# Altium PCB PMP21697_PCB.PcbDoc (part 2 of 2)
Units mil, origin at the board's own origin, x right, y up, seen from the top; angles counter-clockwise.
Board outline 4950 x 3450 mil, 6 copper layers (Top Layer, Signal Layer 1, Signal Layer 2, Signal Layer 3, Signal Layer 4, Bottom Layer), stack 60.502 mil thick; 163 components, 60 nets, 332 pads, 953 vias.
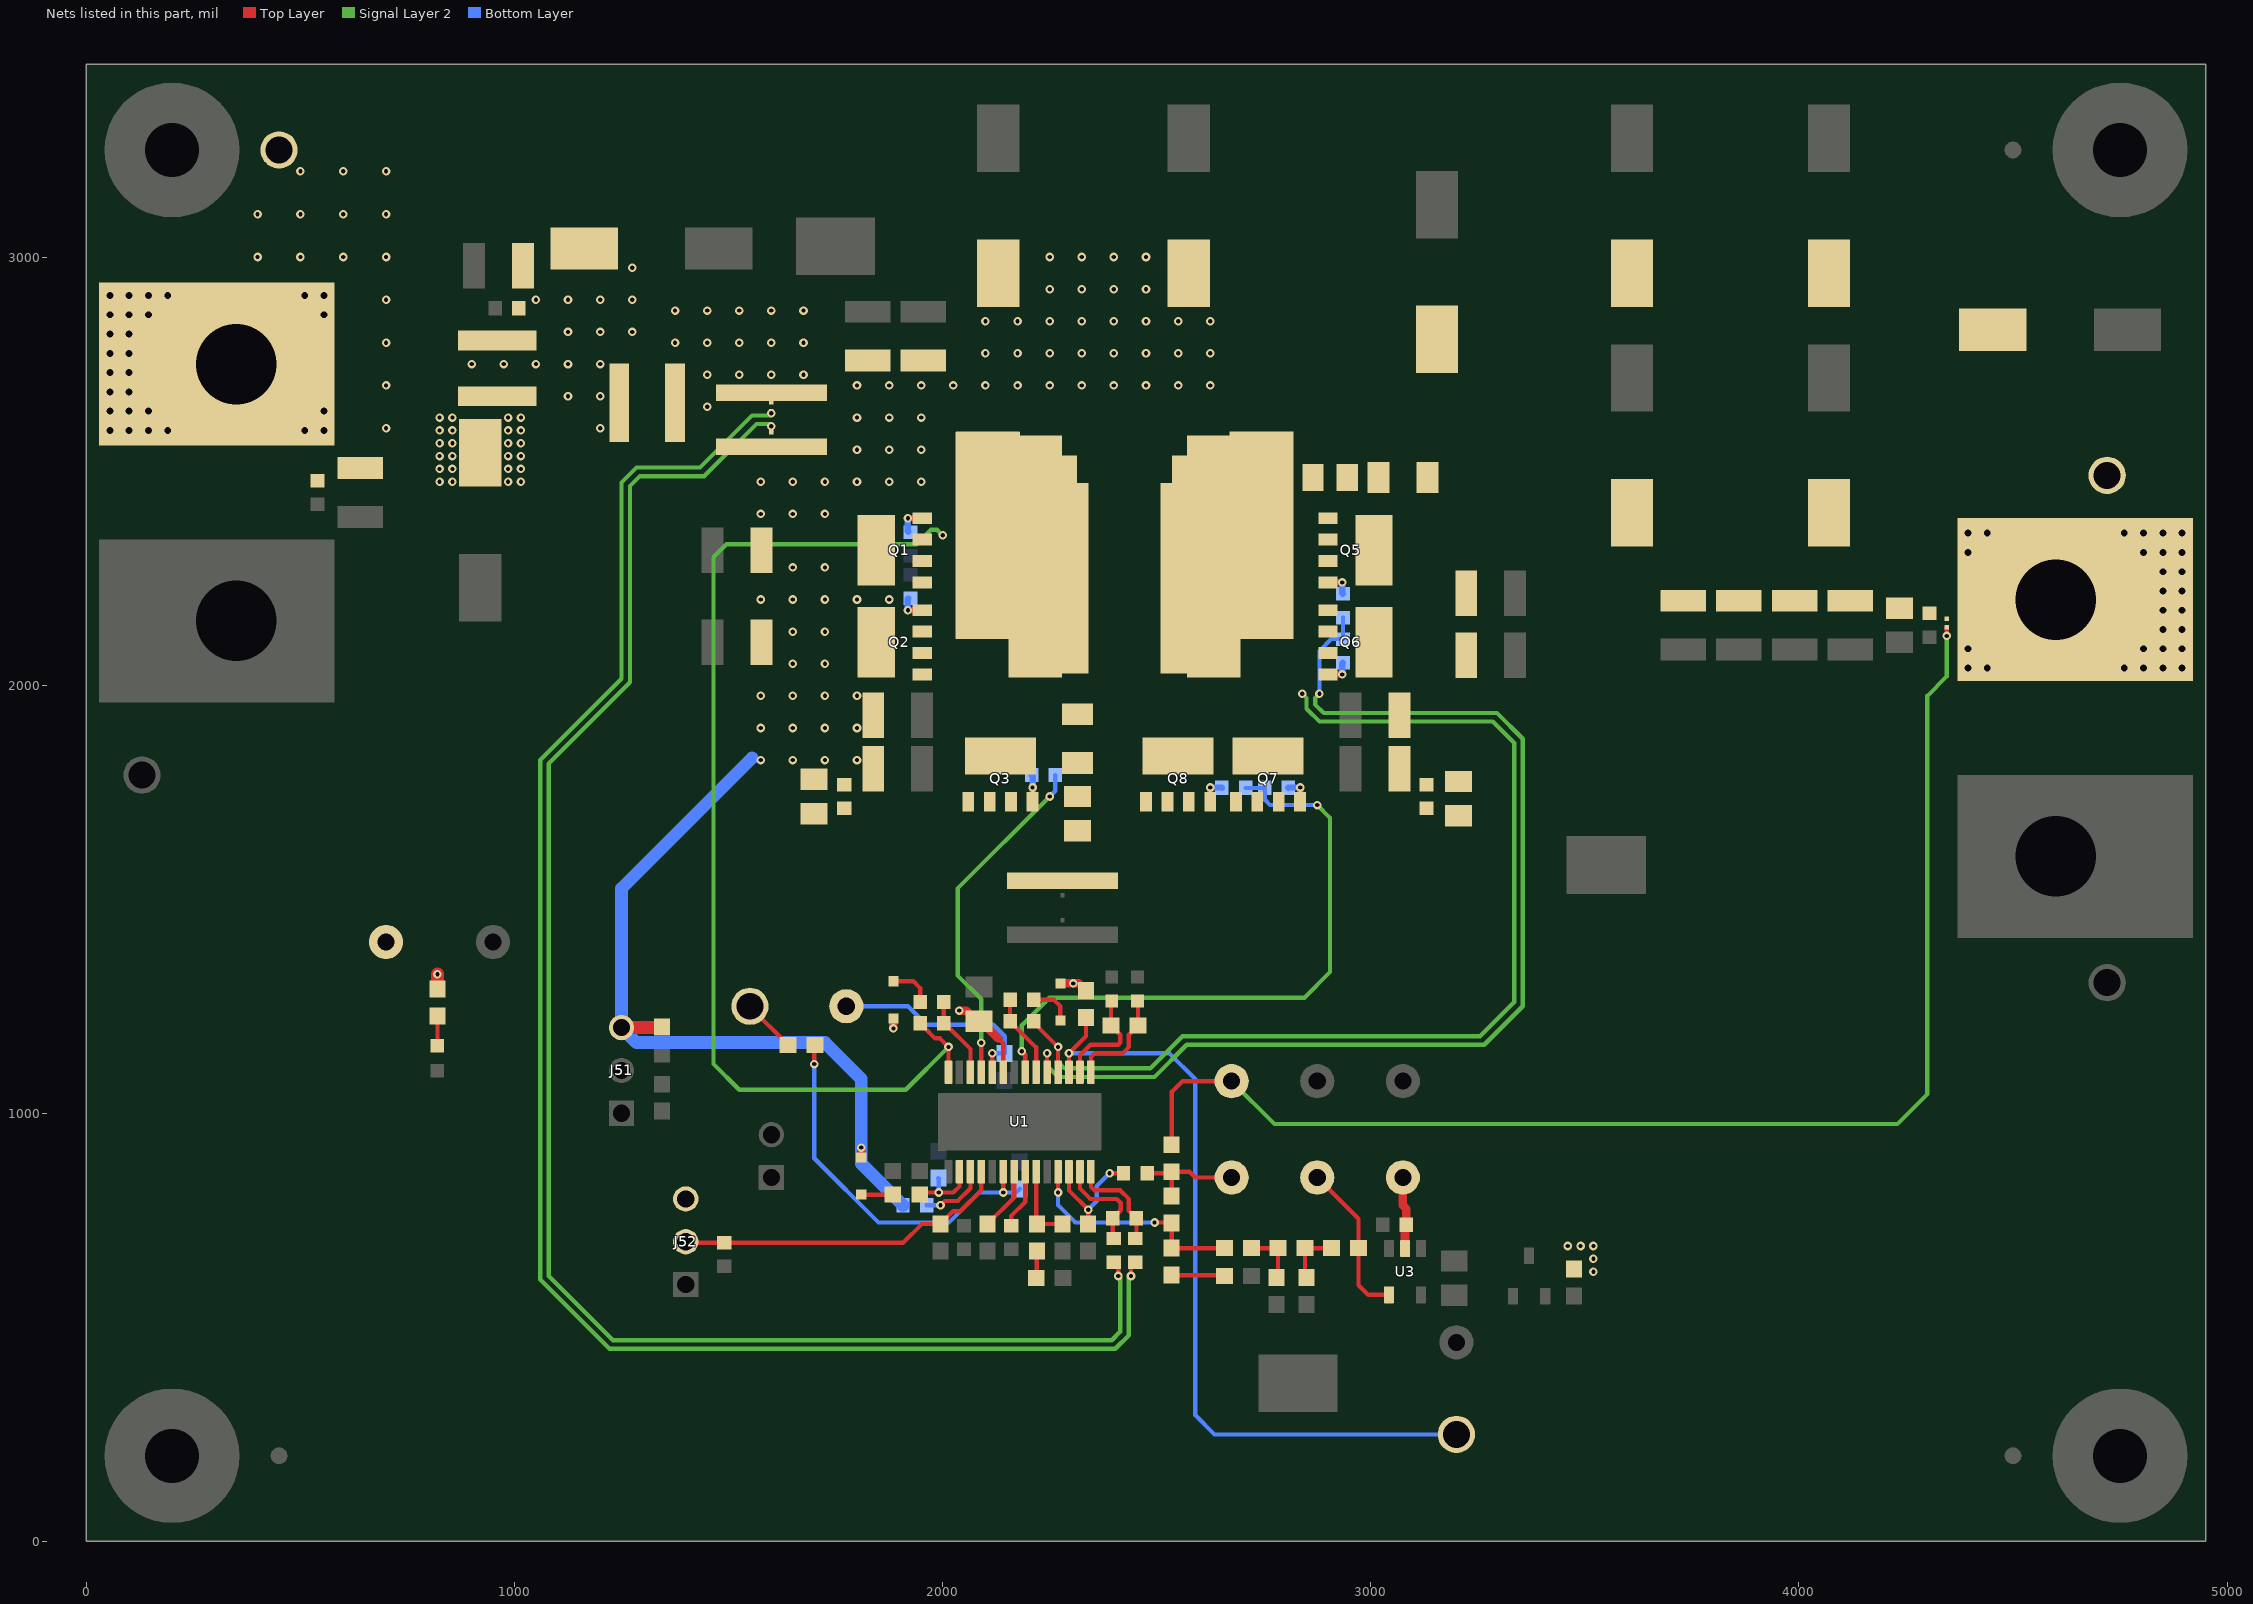
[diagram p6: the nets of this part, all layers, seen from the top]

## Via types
v1: diameter 20, hole 10, Top Layer to Bottom Layer, tented both sides, 820 vias
v2: diameter 32, hole 16, Top Layer to Bottom Layer, 112 vias
v3: diameter 19.68, hole 7.87, Top Layer to Bottom Layer, tented both sides, 12 vias
v4: diameter 19.68, hole 7.87, Top Layer to Bottom Layer, 9 vias

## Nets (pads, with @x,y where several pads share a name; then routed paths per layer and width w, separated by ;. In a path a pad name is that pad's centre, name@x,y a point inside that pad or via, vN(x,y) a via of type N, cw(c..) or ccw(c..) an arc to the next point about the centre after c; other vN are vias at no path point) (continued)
HO2: R15.2 R16.2 U1.19 | length 2652
  Top Layer w10: U1.19@2243.98,1096.14 v1(2243.98,1140)
  Signal Layer 2 w10: v1(2243.98,1140) 2243.98,1111.02 2270,1085 2495,1085 2570,1160 3265,1160 3355,1250 3355,1875 3295,1935 2890,1935 2870,1955 2870,1970 v1(2880,1980)
  Bottom Layer w10: v1(2880,1980) 2880,2080 2907.56,2107.56 R16.2@2935,2107.56 R15.2@2935,2157.93
LO1: R13.2 U1.25 | length 811.4
  Top Layer w10: U1.25@2090.43,1096.14 v1(2090.43,1165)
  Signal Layer 2 w10: v1(2090.43,1165) 2090.43,1266.57 2035,1322 2035,1525 v1(2250,1740)
  Bottom Layer w10: v1(2250,1740) 2263.35,1753.35 R13.2@2263.35,1790
LO2: R17.2 R18.2 U1.21 | length 1486.8
  Top Layer w10: v1(2185,1145) 2192.8,1137.2 U1.21@2192.8,1096.14
  Signal Layer 2 w10: v1(2185,1145) 2185,1205.67 2249.33,1270 2845,1270 2905,1330 2905,1690 v1(2875,1720)
  Bottom Layer w10: R18.2@2707.56,1760 R17.2@2752.44,1760 2752.44,1732.56 2765,1720 v1(2875,1720)
MODE: C64.2 J52.2 R53.2 U1.4 | length 785.8
  Top Layer w10: J52.2@1400,700 1402.44,697.56 R53.2@1490,697.56 1907.56,697.56 1951.5,741.5 C64.2@1995,741.5 2024.53,771.02 2041.02,771.02 2090.43,820.43 U1.4@2090.43,863.86
NetC1_1: C1.1 C2.1 C3.1 L11.1 T1.1 TP1.1
  other v1: 825,2475 855,2475 985,2475 1015,2475 825,2505 855,2505 985,2505 1015,2505 825,2535 855,2535 985,2535 1015,2535 825,2565 855,2565 985,2565 1015,2565 825,2595 855,2595 985,2595 1015,2595 700,2600 825,2625 855,2625 985,2625 1015,2625 700,2700 700,2800 700,2900 400,3000 500,3000 600,3000 700,3000 400,3100 500,3100 600,3100 700,3100 500,3200 600,3200 700,3200
  other v2: 55,2595 100,2595 145,2595 190,2595 510,2595 555,2595 55,2640 100,2640 145,2640 555,2640 55,2685 100,2685 55,2730 100,2730 55,2775 100,2775 55,2820 100,2820 55,2865 100,2865 145,2865 555,2865 55,2910 100,2910 145,2910 190,2910 510,2910 555,2910
NetC4_1: C4.1 C5.1 C6.1 L11.2 L22.1
  other v1: 1200,2600 1125,2675 1200,2675 900,2750 975,2750 1050,2750 1125,2750 1200,2750 1125,2825 1200,2825 1275,2825 1050,2900 1125,2900 1200,2900 1275,2900 1275,2975
NetC19_1: C19.1 R19.1
NetC19_2: C19.2 C37.2 C38.2 C39.2 C40.2 NT8.2 Q3.1 Q3.2 Q3.3 Q7.1 Q7.2 Q7.3 Q8.1 Q8.2 Q8.3 R8.2
NetC20_1: C20.1 R20.1
NetC51_1: C51.1 R63.1 U1.2 | length 169.3
  Top Layer w10: R63.1@1946.5,810 1951.5,815 v1(1991,815) 2025,815 2039.25,829.25 U1.2@2039.25,863.86
  Bottom Layer w10: C51.1@1990,848.5 1991,847.5 v1(1991,815)
NetC53_2: C53.2 R73.1 U1.26 | length 191.1
  Top Layer w10: R73.1@2002.56,1260 C53.2@2002.56,1210 2005,1210 2064.84,1150.16 U1.26@2064.84,1096.14
NetC54_1: C54.1 R74.1 U1.20 | length 194.1
  Top Layer w10: R74.1@2157.44,1265 C54.1@2157.44,1215 2218.39,1154.06 U1.20@2218.39,1096.14
NetC55_1: C55.1 TP56.1 U1.24 | length 511.8
  Top Layer w10: U1.24@2116.02,1096.14 v1(2116.02,1140)
  Bottom Layer w10: TP56.1@1775,1250 1919.25,1250 1962.56,1206.69 2118.31,1206.69 2145,1180 C55.1@2145,1140 v1(2116.02,1140)
NetC56_2: C56.2 R64.2 U1.12 | length 279.1
  Top Layer w10: U1.12@2295.16,863.86 2295.16,819.84 v1(2340,775) C56.2@2340,741.5 ; v1(2390,860) R64.2@2422.44,860
  Bottom Layer w10: v1(2340,775) 2360,795 2360,830 v1(2390,860)
NetC57_1: C57.1 R68.2 U1.6 | length 889.1
  Top Layer w10: v1(1700,1115) 1700,1158.5 C57.1@1701.5,1160 ; v1(2141.61,815) U1.6@2141.61,863.86
  Bottom Layer w10: v1(1700,1115) 1700,895 1850,745 2015,745 2085,815 v1(2141.61,815) 2171.5,815 R68.2@2180,823.5
NetC57_2: C57.2 TP51.1 | length 126.7
  Top Layer w10: TP51.1@1550,1250 1550,1248.5 C57.2@1638.5,1160
NetC59_1: C59.1 C65.1 U1.9 | length 183
  Top Layer w10: U1.9@2218.39,863.86 2218.39,743.11 C59.1@2220,741.5 C65.1@2280,741.5
NetC59_2: C59.2 R67.2 | length 64.1
  Top Layer w10: R67.2@2218.5,615 2220,616.5 C59.2@2220,678.5
NetC60_1: C60.1 R58.2 R59.1 | length 132
  Top Layer w10: R58.2@2721.5,685 R59.1@2783.5,685 2783.5,620 C60.1@2780,616.5
NetC61_1: C61.1 R59.2 R60.1 | length 132
  Top Layer w10: C61.1@2850,616.5 2846.5,620 R59.2@2846.5,685 R60.1@2908.5,685
NetC66_1: C66.1 R71.2 U1.14 | length 236.8
  Top Layer w10: U1.14@2346.34,863.86 2346.34,828.15 2354.49,820 2415,820 2435,800 2435,772.56 C66.1@2452.56,755 2452.56,710.12 R71.2@2450,707.56
NetC66_2: C66.2 R72.2 U1.13 | length 240.5
  Top Layer w10: U1.13@2320.75,863.86 2320.75,824.25 2345,800 2406.72,800 2415.86,790.86 2415.86,773.42 C66.2@2397.44,755 2397.44,710.12 R72.2@2400,707.56
NetC67_1: C67.1 U1.8 | length 139.9
  Top Layer w10: C67.1@2160,737.56 2160,760 2192.8,792.8 U1.8@2192.8,863.86
NetC68_1: C68.1 U1.7 | length 148.1
  Top Layer w10: C68.1@2105,741.5 2167.2,803.7 U1.7@2167.2,863.86
NetC69_1: C69.1 R69.2 U1.16 | length 252.5
  Top Layer w10: U1.16@2320.75,1096.14 2320.75,1135.75 2345,1160 2410,1160 2415,1165 2415,1183.5 C69.1@2393.5,1205 2393.5,1260.5 R69.2@2395,1262
NetC69_2: C69.2 R70.2 U1.15 | length 250.2
  Top Layer w10: U1.15@2346.34,1096.14 2346.34,1131.34 2355,1140 2420,1140 2435,1155 2435,1183.5 C69.2@2456.5,1205 2456.5,1260.5 R70.2@2455,1262
NetD51_1: D51.1 R73.2 | length 101.5
  Top Layer w10: D51.1@1885,1308.31 1931.69,1308.31 1947.44,1292.56 R73.2@1947.44,1260
NetD52_1: D52.1 R74.2 | length 102
  Top Layer w10: R74.2@2212.56,1265 2260,1265 2275,1250 D52.1@2275,1216.69
NetD53_1: D53.1 R63.2 | length 73.5
  Top Layer w10: D53.1@1810,810 R63.2@1883.5,810
NetD75_1: D75.1 R75.1 | length 69
  Top Layer w10: D75.1@820,1158.23 R75.1@820,1227.2
NetL22_2: L22.2 NT1.2 R1.1
  other v1: 1450,2650 1450,2725 1525,2725 1600,2725 1675,2725 1375,2800 1450,2800 1525,2800 1600,2800 1675,2800 1375,2875 1450,2875 1525,2875 1600,2875 1675,2875
NetQ1_4: Q1.4 R11.1 | length 65.1
  Top Layer w15: v1(1919,2390) Q1.4@1952.28,2390
  Bottom Layer w15: v1(1919,2390) 1919,2359.57 R11.1@1920,2358.57
NetQ2_4: Q2.4 R12.1 | length 61.1
  Top Layer w15: v1(1919,2175) Q2.4@1952.28,2175
  Bottom Layer w15: v1(1919,2175) 1919,2201.44 R12.1@1920,2202.44
NetQ3_4: Q3.4 R13.1 | length 63
  Top Layer w15: Q3.4@2210,1727.72 v1(2210,1761)
  Bottom Layer w15: R13.1@2208.23,1790 2210,1788.23 v1(2210,1761)
NetQ5_4: Q5.4 R15.1 | length 60.9
  Top Layer w15: Q5.4@2900,2240 v1(2933.28,2240)
  Bottom Layer w15: v1(2933.28,2240) 2933.28,2214.76 R15.1@2935,2213.05
NetQ6_4: Q6.4 R16.1 | length 61.4
  Top Layer w15: Q6.4@2900,2025 v1(2933.28,2025)
  Bottom Layer w15: v1(2933.28,2025) 2933.28,2050.72 R16.1@2935,2052.44
NetQ7_4: Q7.4 R17.1 | length 61.1
  Top Layer w15: Q7.4@2835,1727.72 v1(2835,1761)
  Bottom Layer w15: R17.1@2807.56,1760 2808.56,1761 v1(2835,1761)
NetQ8_4: Q8.4 R18.1 | length 61.1
  Top Layer w15: Q8.4@2625,1727.72 v1(2625,1761)
  Bottom Layer w15: v1(2625,1761) 2651.44,1761 R18.1@2652.44,1760
NetR54_1: R54.1 R55.2 R64.1 TP53.1 | length 261.5
  Top Layer w10: R64.1@2477.56,860 2531.5,860 R54.1@2535,863.5 ; R55.2@2535,806.5 R54.1@2535,863.5 ; TP53.1@2675,850 2590,850 2576.5,863.5 R54.1@2535,863.5
NetR55_1: R55.1 R56.2 R58.1 U1.11 | length 543.2
  Top Layer w10: v1(2269.57,815) U1.11@2269.57,863.86 ; v1(2495,745) 2533.5,745 R55.1@2535,743.5 R56.2@2535,685 R58.1@2658.5,685
  Bottom Layer w10: v1(2269.57,815) 2269.57,785.43 2310,745 v1(2495,745)
NetR56_1: R56.1 R57.2 | length 124.3
  Top Layer w10: R56.1@2535,622.01 2656.5,622.01 R57.2@2658.5,620
NetR60_2: R60.2 TP70.1 U3.4 | length 371.9
  Top Layer w10: TP70.1@2875,850 2971.5,753.5 R60.2@2971.5,685 2971.5,598.5 2994.13,575.87 U3.4@3042.6,575.87
NetR65_1: R65.1 U1.3 | length 157.8
  Top Layer w10: v1(1995,785) 2005,795 2035,795 2064.84,824.84 U1.3@2064.84,863.86
  Bottom Layer w10: R65.1@1962.56,785 v1(1995,785)
NetR66_1: R66.1 TP57.1 U1.17 | length 1877.2
  Top Layer w10: U1.17@2295.16,1096.14 v1(2295.16,1140) 2295.16,1140.16 2335,1180 R66.1@2335,1223.5
  Bottom Layer w10: v1(2295.16,1140) 2530,1140 2590,1080 2590,295 2635,250 TP57.1@3200,250
SW1: C53.1 L1.1 L2.1 L3.1 L4.1 Q1.1 Q1.2 Q1.3 Q2.1 Q2.2 Q2.3 Q3.5 R19.2 U1.28 | length 2499.3
  Top Layer w10: C53.1@1957.44,1200 1982.44,1175 1993.66,1175 v1(2013.66,1155) U1.28@2013.66,1096.14
  Signal Layer 2 w10: v1(2000,2350) 1987,2363 1973,2363 1939,2329 1495.36,2329 1465,2298.64 1465,1115 1525,1055 1913.66,1055 v1(2013.66,1155)
SW2: C20.2 C54.2 L1.2 L2.2 L3.2 L4.2 Q5.1 Q5.2 Q5.3 Q6.1 Q6.2 Q6.3 Q7.5 Q8.5 U1.18 | length 2475.3
  Top Layer w10: C54.2@2212.56,1215 2212.56,1212.01 v1(2269.57,1155) U1.18@2269.57,1096.14
  Signal Layer 2 w10: v1(2269.57,1155) 2269.57,1120.43 2285,1105 2485,1105 2560,1180 3255,1180 3335,1260 3335,1865 3285,1915 2880,1915 2850,1945 2850,1970 v1(2840,1980)
VCC: C52.2 D51.2 D52.2 J52.3 R62.1 R66.2 R75.2 TP55.1 U1.23 | length 326.7
  Top Layer w10: 2130,1175 2141.61,1163.39 U1.23@2141.61,1096.14
  Top Layer w20: v1(1885,1198.31) D51.2@1885,1221.69 ; v1(2039,1240) 2055,1240 2085,1210 2095,1210 2130,1175 ; D52.2@2275,1303.31 v1(2305,1303.31) 2318.19,1303.31 R66.2@2335,1286.5
  Top Layer w30: R75.2@820,1290.2 v1(820,1325)
  other v1: 3520,630 3520,660 3460,690 3490,690 3520,690
VIN: C7.1 C8.1 C13.1 C14.1 C15.1 C16.1 C17.1 C18.1 C37.1 C39.1 D53.2 J51.3 NT2.2 Q1.5 Q2.5 R1.2 R51.2 R65.2 | length 1820.4
  Top Layer w20: D53.2@1810,896.61 v1(1810,920)
  Top Layer w30: J51.3@1250,1200 1343.5,1200 R51.2@1345,1201.5
  Bottom Layer w30: 1555,1830 1250,1525 J51.3@1250,1200 1285,1165 1725,1165 1810,1080 v1(1810,920) 1810,882.44 R65.2@1907.44,785
  other v1: 1575,1825 1650,1825 1725,1825 1800,1825 1575,1900 1650,1900 1725,1900 1800,1900 1575,1975 1650,1975 1725,1975 1800,1975 1650,2050 1725,2050 1650,2125 1725,2125 1575,2200 1650,2200 1725,2200 1800,2200 1875,2200 1650,2275 1725,2275 1575,2400 1650,2400 1725,2400 1575,2475 1650,2475 1725,2475 1800,2475 1875,2475 1950,2475 1800,2550 1875,2550 1950,2550 1800,2625 1875,2625 1950,2625 1800,2700 1875,2700 1950,2700 2025,2700 2100,2700 2175,2700 2250,2700 2325,2700 2400,2700 2475,2700 2550,2700 2625,2700 2100,2775 2175,2775 2250,2775 2325,2775 2400,2775 2475,2775 2550,2775 2625,2775 2100,2850 2175,2850 2250,2850 2325,2850 2400,2850 2475,2850 2550,2850 2625,2850 2250,2925 2325,2925 2400,2925 2475,2925 2250,3000 2325,3000 2400,3000 2475,3000
VISNS+: NT1.1 R71.1 | length 3993.8
  Top Layer w10: v1(1600,2635) NT1.1@1600,2640 ; v1(2440,620) 2440,641.95 R71.1@2450,651.95
  Signal Layer 2 w10: v1(1600,2635) 1595,2630 1555,2630 1433.15,2508.15 1284.87,2508.15 1250,2473.28 1250,2015 1060,1825 1060,611.72 1221.72,450 2403.28,450 2435,481.72 2435,615 v1(2440,620)
VISNS-: NT2.1 R72.1 | length 3904.3
  Top Layer w10: NT2.1@1600,2590.65 v1(1600,2605) ; R72.1@2400,652.44 2410,642.44 v1(2410,620)
  Signal Layer 2 w10: v1(1600,2605) 1595,2610 1565,2610 1443.15,2488.15 1293.15,2488.15 1270,2465 1270,2006.72 1080,1816.72 1080,620 1230,470 2395,470 2415,490 2415,615 v1(2410,620)
Vosns: NT3.2 R54.2 TP52.1 | length 3077.9
  Top Layer w10: R54.2@2535,926.5 2535,1050 2560,1075 TP52.1@2675,1075 ; v1(4345,2115) NT3.2@4345,2135
  Signal Layer 2 w10: TP52.1@2675,1075 2775,975 4230,975 4300,1045 4300,1975 4345,2020 v1(4345,2115)
VOUT: C21.1 C22.1 C23.1 C24.1 C25.1 C26.1 C27.1 C28.1 C29.1 C30.1 C31.1 C32.1 C33.1 C34.1 C35.1 C36.1 C38.1 C40.1 NT3.1 Q5.5 Q6.5 R20.2 T3.1 TP5.1
  other v2: 4395,2040 4440,2040 4760,2040 4805,2040 4850,2040 4895,2040 4395,2085 4805,2085 4850,2085 4895,2085 4850,2130 4895,2130 4850,2175 4895,2175 4850,2220 4895,2220 4850,2265 4895,2265 4395,2310 4805,2310 4850,2310 4895,2310 4395,2355 4440,2355 4760,2355 4805,2355 4850,2355 4895,2355
VoutPWM: R61.2 TP61.1 U3.2 | length 170.1
  Top Layer w20: TP61.1@3075,850 3075,785 3082.56,777.44 R61.2@3082.56,740 3080,737.44 U3.2@3080,684.13
pads on no net: FID1.1 FID2.1 FID3.1 FID4.1 FID5.1 FID6.1 H1.1 H2.1 H3.1 H4.1 H5.0 H6.0 H7.0 H8.0 LBL1.0 U1.29@2180,980 U3.1

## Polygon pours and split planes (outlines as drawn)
GND on Top Layer "Layer 1 - Top Layer - GND" (solid, remove dead copper, pour order 10): 20,20 4930,20 4930,3430 20,3430
VOUT on Top Layer "Layer 1 - Top Layer - VOUT" (solid, pour order 0): 4920,2010 4370,2010 4370,2140 4360,2150 3545,2150 3415,2280 3385,2310 3290,2310 3265,2285 3265,1925 3265,1765 3245,1745 3040,1745 3030,1755 3030,1855 3030,1980 3005,2005 2970,2005 2960,2015 2960,2400 2980,2420 3055,2420 3075,2440 3075,2865 3115,2905 3245,2905 3440,3100 3650,3100 4480,3100 4600,2980 4600,2785 4765,2620 4920,2465 4920,2390
GND on Signal Layer 4 "Layer 5 - PWR - GND" (solid, remove dead copper, pour order 14): 20,20 4930,20 4930,3430 20,3430
VCC on Signal Layer 4 "Layer 5 - PWR - VCC" (solid, remove dead copper, pour order 2): 655,1440 655,595 1100,150 3375,150 3550,325 3550,1050 3375,1225 2425,1225 2327,1323 2148,1323 2125,1300 1875,1300 1825,1350 1325,1350 1200,1475 1150,1525 975,1525 740,1525
GND on Signal Layer 1 "Layer 2 - GND - GND" (solid, remove dead copper, pour order 4): 20,20 4930,20 4930,3430 20,3430
GND on Signal Layer 3 "Layer 4 - GND - GND" (solid, remove dead copper, pour order 6): 20,20 4930,20 4930,3430 20,3430
GND on Signal Layer 2 "Layer 3 - Sensitive - GND" (solid, remove dead copper, pour order 8): 20,20 4930,20 4930,3430 20,3430
GND on Bottom Layer "Layer 6 - Bottom Layer - GND" (solid, remove dead copper, pour order 12): 20,20 4930,20 4930,3430 20,3430

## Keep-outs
Keep-Out Layer:
  text ".Layer_Name" at 577,-858.49 h60

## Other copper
Top Layer:
  pour cut-out: 3052.75,541.2 3115,540.79 3115,615.29 3057.23,615.29 3052.75,610.81
  pour cut-out: 1205.09,1200 1205.09,1100 1225,1100 1225,1200
  pour cut-out: 825,2775 825,2845.29 860,2845.29 860,2775
  region net NetC19_1: 2270,1720 2280,1710 2350,1710 2360,1720 2360,1840 2350,1850 2280,1850 2270,1840
  region net NetC19_2: 1655,1713.54 1655,1595 1725,1525 2985,1525 3180,1525 3250,1595 3250,1713.54 3233.54,1730 3025,1730 2920,1730 2900,1710 2875,1685 2825,1685 2805,1705 2805,1750 2795,1760 2675,1760 2665,1750 2665,1700 2650,1685 2605,1685 2590,1700 2590,1750 2580,1760 2430,1760 2355,1685 2195,1685 2180,1700 2180,1745 2165,1760 2035,1760 2005,1730 1671.46,1730
  region net VIN: 1890,1750 1890,1995 1890,2400 1910,2420 1995,2420 2010,2435 2010,2600 2060,2650 2602.4,2650 2640,2687.6 2640,3030 2600,3070 2080,3070 2040,3030 2040,2835 2015,2810 1790,2810 1770,2790 1770,2610 1737,2577 1472,2577 1450,2555 1450,2470 1540,2380 1540,1820 1610,1750
  region net SW1: 2380,2545 2380,1905 2345,1870 2270,1870 2245,1845 2245,1815 2220,1790 2045,1790 2015,1820 2015,1985 2000,2000 1930,2000 1920,2010 1920,2130 1930,2140 1985,2140 1995,2150 1995,2210 1985,2220 1930,2220 1920,2230 1920,2350 1930,2360 2005,2360 2030,2385 2030,2595 2065,2630 2295,2630
  region net SW2: 2460,1790 2845,1790 2855,1800 2855,2050 2865,2060 2925,2060 2935,2070 2935,2180 2925,2190 2875,2190 2855,2210 2855,2255 2875,2275 2925,2275 2935,2285 2935,2395 2900,2430 2900,2610 2880,2630 2535,2630 2450,2545 2450,1800
  region net NetL22_2: 1400,2565 1495,2660 1735,2660 1745,2670 1745,2860 1720,2885 1370,2885 1345,2860 1345,2575 1355,2565
  pour cut-out: 2370.53,1047 2370.53,1131 1989.47,1131 1989.47,1047
  pour cut-out: 1961.46,913 1961.46,885 2391.69,885 2391.69,913
  pour cut-out: 1202,2548 1434.71,2548 1434.71,2900.29 1202,2900.29
  region net VOUT: 4320,2150 4360,2150 4370,2140 4370,2175 4320,2175
  region net GND: 3540,2615 4140,2615 4140,2820 3540,2820
  region net NetC4_1: 860,2765 900,2725 1060,2725 1130,2655 1130,2600 1180,2550 1255,2550 1305,2600 1305,3020 1250,3075 1030,3075 990,3035 990,2855 965,2830 860,2830
  region net NetC1_1: 30,2500 70,2460 1050,2460 1100,2510 1100,2655 1050,2705 890,2705 820,2775 820,3250 770,3300 430,3300 380,3250 380,3100 330,3050 80,3050 30,3000
  region net 2v5: 3090,476.77 3150.76,416 3456,416 3515,475 3515,580 3495,600 3110,600 3090,580
  region net VCC: 3445,615 3445,695 3455,705 3525,705 3535,695 3535,625 3525,615
  region net NetC20_1: 3055.32,2450.32 3045,2440 2925,2440 2915,2450 2915,2520 2925,2530 3045,2530 3055.32,2519.68
  region net GND: 1990,1985 2000,1975 2000,1755 1990,1745 1915,1745 1905,1755 1905,1975 1915,1985
  region net GND: 3005,1755 2995,1745 2880,1745 2875,1750 2875,1905 2905,1935 2905,1975 2915,1985 2995,1985 3005,1975
  text ".Layer_Name" at 577,-858.49 h60
Signal Layer 1:
  text ".Layer_Name" at 577,-858.49 h60
Signal Layer 2:
  text ".Layer_Name" at 577,-858.49 h60
Signal Layer 3:
  text ".Layer_Name" at 577,-858.49 h60
Signal Layer 4:
  pour cut-out: 860,2845.29 825,2845.29 825,2775 860,2775
  region net NetL22_2: 1400,2565 1495,2660 1735,2660 1745,2670 1745,2860 1720,2885 1370,2885 1345,2860 1345,2575 1355,2565
  pour cut-out: 1997.19,903.48 2362.81,903.59 2362.81,1056.51 1997.19,1056.51
  pour cut-out: 2710,265 2950,265 2950,475 2710,475
  pour cut-out: 1202,2548 1434.71,2548 1434.71,2900.29 1202,2900.29
  region net NetC4_1: 860,2765 900,2725 1060,2725 1130,2655 1130,2600 1180,2550 1255,2550 1305,2600 1305,3020 1250,3075 1030,3075 990,3035 990,2855 965,2830 860,2830
  region net NetC1_1: 30,2500 70,2460 1050,2460 1100,2510 1100,2655 1050,2705 890,2705 820,2775 820,3250 770,3300 430,3300 380,3250 380,3100 330,3050 80,3050 30,3000
  region net VIN: 1890,1750 1890,1995 1890,2400 1910,2420 1995,2420 2010,2435 2010,2600 2060,2650 2602.4,2650 2640,2687.6 2640,3030 2600,3070 2080,3070 2040,3030 2040,2835 2015,2810 1790,2810 1770,2790 1770,2610 1737,2577 1472,2577 1450,2555 1450,2470 1540,2380 1540,1820 1610,1750
  text ".Layer_Name" at 577,-858.49 h60
Bottom Layer:
  pour cut-out: 1205.09,1200 1205.09,1100 1235,1100 1235,1200
  pour cut-out: 860,2845.29 825,2845.29 825,2775 860,2775
  region net NetL22_2: 1400,2565 1495,2660 1735,2660 1745,2670 1745,2860 1720,2885 1370,2885 1345,2860 1345,2575 1355,2565
  pour cut-out: 1202,2548 1434.71,2548 1434.71,2900.29 1202,2900.29
  region net NetC4_1: 860,2765 900,2725 1060,2725 1130,2655 1130,2600 1180,2550 1255,2550 1305,2600 1305,3020 1250,3075 1030,3075 990,3035 990,2855 965,2830 860,2830
  region net NetC1_1: 30,2500 70,2460 1050,2460 1100,2510 1100,2655 1050,2705 890,2705 820,2775 820,3250 770,3300 430,3300 380,3250 380,3100 330,3050 80,3050 30,3000
  region net VIN: 1890,1750 1890,1995 1890,2400 1910,2420 1995,2420 2010,2435 2010,2600 2060,2650 2602.4,2650 2640,2687.6 2640,3030 2600,3070 2080,3070 2040,3030 2040,2835 2015,2810 1790,2810 1770,2790 1770,2610 1737,2577 1472,2577 1450,2555 1450,2470 1540,2380 1540,1820 1610,1750
  text ".Layer_Name" at 577,-858.49 h60

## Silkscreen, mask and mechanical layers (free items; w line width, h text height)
Top Overlay:
  text "Bat+" at 140,2970 h60
  text "SW1" at 2085,2710 h60
  text "SW2" at 2655,2710 h60
  text "Vout" at 4515,2475 h60
  text "GND" at 260,1870 h60
  text "Vcc 7.3V" at 595,1465 h60
  text "GND" at 890,1465 h60
  text "SYNC" at 1480,1355 h60
  text "Ext_Bias" at 1670,1355 h60
  text "GND" at 4520,1285 h60
  text "Vin" at 1100,1185 h60
  text "Enable" at 1010,1085 h60
  text "Power On" at 910,1060 h60 r90
  text "BodeV2" at 2780,1020 h60 r90
  text "GND" at 2985,1020 h60 r90
  text "GND" at 3185,1020 h60 r90
  text "GND" at 1065,980 h60
  text "PWM" at 3185,800 h60 r90
  text "BodeV1" at 2780,795 h60 r90
  text "\PWM" at 2985,785 h60 r90
  text "VCC" at 1220,780 h60
  text "dither disable" at 1525,740 h60 r90
  text "MODE" at 1175,680 h60
  text "GND" at 1215,580 h60
  text "2.5V" at 3285,420 h60
  text "PowerGood" at 3295,210 h60
  text ".Layer_Name" at 577,-858.49 h60
Bottom Overlay:
  text ".Layer_Name" at 577,-858.49 h60
Top Paste:
  text ".Layer_Name" at 577,-858.49 h60
Bottom Paste:
  text ".Layer_Name" at 577,-858.49 h60
Top Solder:
  text ".Layer_Name" at 577,-858.49 h60
  text ".Layer_Name" at 577,-858.49 h60
Bottom Solder:
  text ".Layer_Name" at 577,-858.49 h60
Drill Guide:
  text ".Layer_Name" at 577,-858.49 h60
M1 Board Outline:
  the board outline again, w10
  text ".Layer_Name" at 577,-858.49 h60
M2 Board Dimensions:
  rectangle: 125,-400 500,-275
  rectangle: 0,-275 125,-150
  lines w7: 0,-275 1000,-275 ; 125,-400 125,-150 ; 250,-400 250,-150 ; 500,-400 500,-150 ; 750,-400 750,-150 ; 0,-400 0,-150 1000,-150 1000,-400 0,-400
  text ".Layer_Name" at 577,-858.49 h60
M3 3D STEP Top:
  text ".Layer_Name" at 577,-858.49 h60
M4 3D STEP Bottom:
  text ".Layer_Name" at 577,-858.49 h60
M5 Assembly Top:
  lines w10: -292,-930.17 6308,-930.17 ; -292,-726.83 6310,-726.83 ; -292,-523.5 -292,-1133.5 3713,-1133.5 6310,-1133.5 6310,-523.5 -291.5,-523.5 -291.5,-1133.5 1284,-1133.5 ; 2173,-1133.5 2173,-523.5 ; 3440,-726.83 3440,-523.5 ; 4280,-726.83 4280,-523.5 ; 4902,-1140 4902,-937.17
  text "COMPONENTS MARKED 'DNP' SHOULD NOT BE POPULATED." at 1153.5,-318.5 h60
  text "ASSEMBLY VARIANT:" at 1153,-434 h60
  text ".VariantName" at 2189,-434 h60
  text "PCB VIEWED FROM TOP SIDE" at -228.5,-655.67 h60
  text "BOARD #:" at 2248,-655.67 h60
  text ".PRJ_Number" at 2793.5,-655.67 h60
  text "REV:" at 3638,-655.67 h60
  text ".PCB_Rev" at 3929.5,-655.67 h60
  text "SVN REV:" at 4476,-655.67 h60
  text ".VersionControl_RevNumber" at 4982,-655.67 h60
  text "TID #:" at 2248,-859 h60
  text ".TID" at 2793.5,-859 h60
  text "PLOT NAME =" at -228.5,-1064.34 h60
  text ".plot_File_Name" at 577,-1064.34 h60
  text "GENERATED    :" at 2250,-1064.34 h60
  text ".Print_Date" at 3119.5,-1064.34 h60
  text ".Print_Time" at 3848.5,-1064.34 h60
  text "TEXAS INSTRUMENTS" at 5113,-1064.34 h60
M6 Assembly Bottom:
  lines w10: -292.5,-727.33 6309.5,-727.33 ; -290.5,-930.67 6309.5,-930.67 ; 1115.5,-1140.5 1115.5,-937.67 ; 1737.5,-727.33 1737.5,-524 ; 2577.5,-727.33 2577.5,-524 ; 3844.5,-1134 3844.5,-524 ; 4733.5,-1134 6309,-1134 6309,-524 -292.5,-524 -292.5,-1134 2304.5,-1134 6309.5,-1134 6309.5,-524
  text "COMPONENTS MARKED 'DNP' SHOULD NOT BE POPULATED." at 6102,-318 h60
  text ".VariantName" at 5058,-434 h60
  text "ASSEMBLY VARIANT:" at 6097,-434 h60
  text ".VersionControl_RevNumber" at 1035.5,-656.17 h60
  text "SVN REV:" at 1541.5,-656.17 h60
  text ".PCB_Rev" at 2088,-656.17 h60
  text "REV:" at 2379.5,-656.17 h60
  text ".PRJ_Number" at 3224,-656.17 h60
  text "BOARD #:" at 3769.5,-656.17 h60
  text "PCB VIEWED FROM BOTTOM SIDE" at 6246,-656.17 h60
  text ".TID" at 3224,-859.5 h60
  text "TID #:" at 3769.5,-859.5 h60
  text "TEXAS INSTRUMENTS" at 904.5,-1064.84 h60
  text ".Print_Time" at 2169,-1064.84 h60
  text ".Print_Date" at 2898,-1064.84 h60
  text "GENERATED    :" at 3767.5,-1064.84 h60
  text ".plot_File_Name" at 5440.5,-1064.84 h60
  text "PLOT NAME =" at 6246,-1064.84 h60
M9 Title Sheet:
  drawing of 57 lines, arcs and shapes, not listed
  text "1" at 739.84,8036.5 h70
  text "2" at 3235.5,8036.5 h70
  text "3" at 5724.84,8036.5 h70
  text "4" at 8231.51,8036.5 h70
  text "5" at 10730.5,8036.5 h70
  text "6" at 13235.5,8036.5 h70
  text "A" at -416.5,6893.5 h70
  text "A" at 14383.5,6893.5 h70
  text "B" at -416.5,4513.5 h70
  text "B" at 14383.5,4513.5 h70
  text "C" at -416.5,2138.5 h70
  text "C" at 14383.5,2138.5 h70
  text "PROJECT TITLE:" at 11343.5,277.5 h45
  text ".PRJ_Title" at 11393.5,144.17 h70
  text "DESIGNED FOR:" at 11343.5,-23.5 h45
  text ".PRJ_Customer" at 11393.5,-163.5 h70
  text "D" at -416.5,-231.5 h70
  text "D" at 14383.5,-231.5 h70
  text "FILE NAME:" at 11343.5,-323.5 h45
  text ".PCB_File_Name_No_Path" at 11393.5,-443.5 h70
  text "Texas Instruments (TI) and/or its licensors do not warrant the accuracy or completeness of this specification" at 6374,-605.34 h45
  text "ENGINEER:" at 11343.5,-613.5 h45
  text "LAYOUT BY:" at 12848.5,-613.5 h45
  text "or any information contained therein. TI and/or its licensors do not warrant that this design will meet" at 6329.01,-718 h45
  text ".PRJ_Engineer" at 11393.5,-768.49 h70
  text ".PCB_Layout" at 12899,-768.49 h70
  text "the specifications, will be suitable for your application or fit for any particular purpose, or will operate in" at 6329.01,-830.67 h45
  text ".Layer_Name" at 577,-858.49 h60
  text "ALTIUM DESIGNER VERSION:" at 12848.5,-923.5 h45
  text "an implementation. TI and/or its licensors do not warrant that the design is production worthy. You should" at 6329.01,-943.33 h45
  text "completely validate and test your design implementation to confirm the system functionality for your application." at 6374,-1056 h45
  text ".print_Scale" at 11393.5,-1056.83 h70
  text ".Application_BuildNumber" at 12899,-1056.83 h70
  text "1" at 739.84,-1263.5 h70
  text "2" at 3235.5,-1263.5 h70
  text "3" at 5724.84,-1263.5 h70
  text "4" at 8231.51,-1263.5 h70
  text "5" at 10730.5,-1263.5 h70
  text "6" at 13235.5,-1263.5 h70
M10 Fab Notes:
  drawing of 189 lines, arcs and shapes, not listed
  text "DESIGN INFORMATION" at 12382.02,6356.17 h60
  text "MIN. TRACK WIDTH:" at 11737.46,6224.05 h60
  text "8" at 12833.7,6224.05 h60
  text "MIL" at 12988.46,6224.05 h60
  text "MIN. CLEARANCE:" at 11737.46,6099.92 h60
  text "0.2" at 12773.7,6099.93 h60
  text "mm" at 12988.46,6099.92 h60
  text "MIN. VIA PAD SIZE:" at 11737.46,5975.8 h60
  text "20" at 12803.71,5975.8 h60
  text "MIL" at 12988.46,5975.8 h60
  text "0.05mm (2MIL)" at 12432.46,5845.9 h60
  text "MINIMUM ANNULAR RING" at 11408.23,5837.67 h60
  text "EXTERNAL" at 13140.46,5837.67 h60
  text "PER" at 11608.23,5727.55 h60
  text "IPC-D-275 CLASS 2 LEVEL C" at 11828.23,5727.54 h60
  text "MIL, HOLES" at 13316.46,5627.07 h60
  text "+/-" at 12924,5618.48 h60
  text "+/-" at 13778,5618.48 h60
  text "REGISTRATION TOLERANCES:" at 11408.23,5617.42 h60
  text "METAL" at 12608,5617.42 h60
  text "5" at 13184.2,5617.42 h60
  text "3" at 14017.2,5617.42 h60
  text "MIL" at 14133.46,5617.42 h60
  text "HOLE SIZE TOLERANCE (UNLESS OTHERWISE SPECIFIED):" at 11408.23,5519.1 h60
  text "+/-" at 13778,5516.23 h60
  text "3" at 14017.2,5515.17 h60
  text "MIL" at 14133.46,5515.17 h60
  text "MATERIAL:" at 11333.46,5377.52 h60
  text "FR-4 High Tg" at 12319.9,5249 h60
  text "X" at 12175.46,5241.01 h60
  text "FR-408" at 11754.46,5236.49 h60
  text "OTHER" at 13242.46,5236.49 h60
  text "62 MIL (1.6mm) +/-10%" at 12074.56,5093.46 h60
  text "X" at 11954.46,5091.01 h60
  text "THICKNESS:" at 11408.23,5085.24 h60
  text "OTHER" at 13359.46,5085.24 h60
  text "TOLERANCE:" at 11408.23,4946.92 h60
  text "X" at 12256.46,4946.92 h60
  text "ANSI IPC-6012 TYPE 3 CLASS 2" at 12434.48,4946.92 h60
  text "OTHER +/-" at 12434.46,4802.73 h60
  text "BOW & TWIST:" at 11408.23,4657.54 h60
  text "X" at 12256.46,4657.54 h60
  text "ANSI IPC-6012 TYPE 3 CLASS 2" at 12434.48,4657.54 h60
  text "OTHER +/-" at 12434.46,4510.85 h60
  text "DRILLING:" at 11333.46,4380.23 h60
  text "NC_DRILL FILES" at 13094.46,4275.04 h60
  text "REFERENCE:" at 11408.23,4271.1 h60
  text "X" at 12065.46,4271.01 h60
  text "AS SHOWN" at 12243.46,4271.1 h60
  text "X" at 12966.46,4271.1 h60
  text "OTHER" at 13392.46,4128.85 h60
  text "PTH COPPER THICKNESS:" at 11407.91,4125.32 h60
  text "X" at 12547.14,4125.32 h60
  text "20-30 um" at 12675.14,4125.32 h60
  text "BOARD FINISH:" at 11333.46,3977.73 h60
  text "SILKSCREEN:" at 11488.68,3867.6 h60
  text "X" at 12446.46,3867.6 h60
  text "TOP" at 12563.46,3867.6 h60
  text "X" at 12956.46,3867.6 h60
  text "BOTTOM" at 13074.46,3867.6 h60
  text "SILKSCREEN COLOR:" at 11488.68,3712.41 h60
  text "X" at 12445.46,3712.41 h60
  text "WHITE" at 12563.46,3712.41 h60
  text "OTHER" at 13074.46,3712.41 h60
  text "X" at 12576.46,3568.96 h60
  text "GREEN" at 12694.46,3568.96 h60
  text "OTHER" at 13312.46,3568.96 h60
  text "SOLDER RESIST COLOR:" at 11488.68,3562.1 h60
  text "X" at 12576.46,3414.71 h60
  text "MATTE" at 12694.46,3414.71 h60
  text "SEMI-GLOSS" at 13312,3414.07 h60
  text "IMMERSION GOLD (ENIG)" at 12394.46,3241.94 h60
  text "ENEPIG" at 13732,3234.72 h60
  text "SURFACE FINISH:" at 11333.46,3233.72 h60
  text "X" at 12216.46,3233.72 h60
  text "IMM. TIN/SILVER OR EQUIV" at 11663,3096.4 h60
  text "OTHER" at 13094.46,3092.47 h60
  text "ARRAY/PANEL:" at 11333.46,2937.09 h60
  text "CUT AND TRIM PER M1 BOARD OUTLINE" at 12394.46,2928.87 h60
  text "N.C. ROUTE" at 12394.46,2792.9 h60
  text "X" at 13082.46,2792.9 h60
  text "V. SCORE" at 13260.46,2792.9 h60
  text "CERTIFICATION:" at 11333.46,2663.77 h60
  text "MATERIALS AND WORKMANSHIP FOR ALL PCBS" at 12058.46,2663.77 h60
  text "TO MEET OR EXCEED THE REQUIREMENTS OF:" at 12058.46,2569.71 h60
  text "X" at 11695.97,2441.08 h60
  text "ANSI IPC-A-600F CLASS ->" at 11823.96,2441.08 h60
  text "X" at 13471.97,2441.08 h60
  text "2" at 13581.96,2441.08 h60
  text "1" at 13266.96,2439.58 h60
  text "3" at 13935.96,2439.58 h60
  text "X" at 12507.97,2293.39 h60
  text "RoHS" at 12635.96,2293.39 h60
  text "OTHER" at 13280.36,2293.39 h60
  text "PER ORDER" at 13677.42,2293.39 h60
  text "ALL BOARDS MUST MEET OR EXCEED UL94-V0 REQUIREMENTS." at 11361,2139.57 h60
  text "PCB MUST BEAR THE UL94V-0 UL REGISTERED MATERIAL ID NUMBER" at 11361,2023.5 h60
  text "ADDITIONAL REQUIREMENTS:" at 11333.46,1854.08 h60
  text "MICROSECTION:" at 11408.23,1746.95 h60
  text "YES" at 12313.96,1746.95 h60
  text "REQUIRED" at 13175.46,1602.62 h60
  text "BARE BOARD ELEC. TEST:" at 11408.23,1599.76 h60
  text "NONE" at 12713.96,1599.76 h60
  text "X" at 13057.46,1599.76 h60
  text "PER ORDER" at 13767.46,1599.76 h60
  text "XX MIL VIAS REQUIRE NON-CONDUCTIVE FILL AND PLANARIZE" at 11576.38,1394.82 h59
  text "XX MIL VIAS REQUIRE CONDUCTIVE FILL AND PLANARIZE" at 11584.38,1290.84 h60
  text "OUTER XX MIL TRACES REQUIRE 50 OHM SINGLE-ENDED IMPEDANCE" at 11583.39,1127.46 h58
  text "LAYER 2 & 3 (INNER LAYERS) XX MIL WIDE, XX MIL SPACE / TRACES REQUIRE 100 OHM DIFFERENTIAL IMPEDANCE" at 11575.39,891.74 h60
  text ".Layer_Name" at 577,-858.49 h60
M11 Gerber Information:
  lines w10: -292,-930.17 6308,-930.17 ; -292,-726.83 6310,-726.83 ; -292,-523.5 -292,-1133.5 3713,-1133.5 6310,-1133.5 6310,-523.5 -291.5,-523.5 -291.5,-1133.5 1284,-1133.5 ; 2173,-1133.5 2173,-523.5 ; 3440,-726.83 3440,-523.5 ; 4280,-726.83 4280,-523.5 ; 4902,-1140 4902,-937.17
  text "ALL ARTWORK VIEWED FROM TOP SIDE" at -228.5,-655.67 h60
  text "BOARD #:" at 2248,-655.67 h60
  text ".PRJ_Number" at 2793.5,-655.67 h60
  text "REV:" at 3638,-655.67 h60
  text ".PCB_Rev" at 3929.5,-655.67 h60
  text "SVN REV:" at 4476,-655.67 h60
  text ".VersionControl_RevNumber" at 4982,-655.67 h60
  text "LAYER NAME =" at -228.5,-858.49 h60
  text "TID #:" at 2248,-859 h60
  text ".TID" at 2793.5,-859 h60
  text "PLOT NAME =" at -228.5,-1064.34 h60
  text ".plot_File_Name" at 577,-1064.34 h60
  text "GENERATED    :" at 2250,-1064.34 h60
  text ".Print_Date" at 3119.5,-1064.34 h60
  text ".Print_Time" at 3848.5,-1064.34 h60
  text "TEXAS INSTRUMENTS" at 5113,-1064.34 h60
M12 Stackup:
  drawing of 399 lines, arcs and shapes, not listed
  text "Layer" at 6527.5,7662.5 h60
  text "Name" at 6937.41,7662.5 h60
  text "Material" at 7877.15,7662.5 h60
  text "Thickness" at 8736.92,7662.5 h60
  text "Constant" at 9386.76,7662.5 h60
  text "Board Layer Stack" at 9956.62,7662.5 h60
  text "1" at 6527.5,7542.5 h60
  text "Top Overlay" at 6937.41,7542.5 h60
  text "2" at 6527.5,7422.5 h60
  text "Top Solder" at 6937.41,7422.5 h60
  text "Solder Resist" at 7877.15,7422.5 h60
  text "0.40mil" at 8736.92,7422.5 h60
  text "3.5" at 9386.76,7422.5 h60
  text "3" at 6527.5,7302.5 h60
  text "Top Layer" at 6937.41,7302.5 h60
  text "Copper" at 7877.15,7302.5 h60
  text "1.42mil" at 8736.92,7302.5 h60
  text "4" at 6527.5,7182.5 h60
  text "Dielectric1" at 6937.41,7182.5 h60
  text "FR-4" at 7877.15,7182.5 h60
  text "7.00mil" at 8736.92,7182.5 h60
  text "4.2" at 9386.76,7182.5 h60
  text "5" at 6527.5,7062.5 h60
  text "Signal Layer 1" at 6937.41,7062.5 h60
  text "Copper" at 7877.15,7062.5 h60
  text "1.42mil" at 8736.92,7062.5 h60
  text "6" at 6527.5,6942.5 h60
  text "Dielectric 2" at 6937.41,6942.5 h60
  text "FR-4" at 7877.15,6942.5 h60
  text "6.00mil" at 8736.92,6942.5 h60
  text "4.2" at 9386.76,6942.5 h60
  text "7" at 6527.5,6822.5 h60
  text "Signal Layer 2" at 6937.41,6822.5 h60
  text "Copper" at 7877.15,6822.5 h60
  text "1.42mil" at 8736.92,6822.5 h60
  text "8" at 6527.5,6702.5 h60
  text "Dielectric 3" at 6937.41,6702.5 h60
  text "FR-4" at 7877.15,6702.5 h60
  text "26.00mil" at 8736.92,6702.5 h60
  text "4.2" at 9386.76,6702.5 h60
  text "9" at 6527.5,6582.5 h60
  text "Signal Layer 3" at 6937.41,6582.5 h60
  text "Copper" at 7877.15,6582.5 h60
  text "1.42mil" at 8736.92,6582.5 h60
  text "10" at 6527.5,6462.5 h60
  text "Dielectric 4" at 6937.41,6462.5 h60
  text "FR-4" at 7877.15,6462.5 h60
  text "6.00mil" at 8736.92,6462.5 h60
  text "4.2" at 9386.76,6462.5 h60
  text "11" at 6527.5,6342.5 h60
  text "Signal Layer 4" at 6937.41,6342.5 h60
  text "Copper" at 7877.15,6342.5 h60
  text "1.42mil" at 8736.92,6342.5 h60
  text "12" at 6527.5,6222.5 h60
  text "Dielectric 5" at 6937.41,6222.5 h60
  text "FR-4" at 7877.15,6222.5 h60
  text "7.00mil" at 8736.92,6222.5 h60
  text "4.2" at 9386.76,6222.5 h60
  text "13" at 6527.5,6102.5 h60
  text "Bottom Layer" at 6937.41,6102.5 h60
  text "Copper" at 7877.15,6102.5 h60
  text "1.42mil" at 8736.92,6102.5 h60
  text "14" at 6527.5,5982.5 h60
  text "Bottom Solder" at 6937.41,5982.5 h60
  text "Solder Resist" at 7877.15,5982.5 h60
  text "0.40mil" at 8736.92,5982.5 h60
  text "3.5" at 9386.76,5982.5 h60
  text "15" at 6527.5,5862.5 h60
  text "Bottom Overlay" at 6937.41,5862.5 h60
  text ".Layer_Name" at 577,-858.49 h60
M13 Component Bodies Top:
  text ".Layer_Name" at 577,-858.49 h60
M14 Component Bodies Bottom:
  text ".Layer_Name" at 577,-858.49 h60
M15 Courtyards Top:
  text ".Layer_Name" at 577,-858.49 h60
M16 Courtyards Bottom:
  text ".Layer_Name" at 577,-858.49 h60
Drill Drawing:
  circle w10: c4695.62,5425.83 r33.33
  lines w10: 4662.29,4525.83 4695.62,4492.5 4728.96,4525.83 4695.62,4559.17 4662.29,4525.83 ; 4662.29,4642.5 4695.62,4659.17 4728.96,4642.5 4712.29,4675.83 4728.96,4709.17 4695.62,4692.5 4662.29,4709.17 4678.96,4675.83 4662.29,4642.5 ; 4662.29,4809.17 4678.96,4809.17 4678.96,4792.5 4712.29,4792.5 4712.29,4809.17 4728.96,4809.17 4728.96,4842.5 4712.29,4842.5 4712.29,4859.17 4678.96,4859.17 4678.96,4842.5 4662.29,4842.5 4662.29,4809.17 ; 4662.29,4959.17 4678.96,4959.17 4695.62,4942.5 4712.29,4959.17 4728.96,4959.17 4712.29,4975.83 4728.96,4992.5 4712.29,4992.5 4695.62,5009.17 4678.96,4992.5 4662.29,4992.5 4678.96,4975.83 4662.29,4959.17 ; 4662.29,5092.5 4728.96,5092.5 4728.96,5159.17 4662.29,5159.17 4662.29,5092.5 ; 4662.29,5309.17 4728.96,5309.17 4695.62,5242.5 4662.29,5309.17
  lines w15: 4602.5,4447.5 11022.76,4447.5 ; 4602.5,5497.5 11022.76,5497.5 ; 5153.38,4297.5 5153.38,5647.5 ; 5753.22,4297.5 5753.22,5647.5 ; 6902.88,4297.5 6902.88,5647.5 ; 7408.76,4297.5 7408.76,5647.5 ; 8142.56,4297.5 8142.56,5647.5 ; 9642.11,4297.5 9642.11,5647.5 ; 10231.96,4297.5 10231.96,5647.5 ; 4602.5,4297.5 11022.76,4297.5 11022.76,5647.5 4602.5,5647.5 4602.5,4297.5
  text "Symbol" at 4692.5,5542.5 h72
  text "Count" at 5198.38,5542.5 h72
  text "Hole Size" at 5798.22,5542.5 h72
  text "Plated" at 6947.88,5542.5 h72
  text "Hole Type" at 7453.76,5542.5 h72
  text "Drill Layer Pair" at 8187.56,5542.5 h72
  text "Via/Pad" at 9687.11,5542.5 h72
  text "Pad Shape" at 10276.96,5542.5 h72
  text "4" at 5198.38,5392.5 h60
  text "125.98mil (3.200mm)" at 5798.22,5392.5 h60
  text "PTH" at 6947.88,5392.5 h60
  text "Round" at 7453.76,5392.5 h60
  text "Top Layer - Bottom Layer" at 8187.56,5392.5 h60
  text "Pad" at 9687.11,5392.5 h60
  text "Rounded" at 10276.96,5392.5 h60
  text "4" at 5198.38,5242.5 h60
  text "188.00mil (4.775mm)" at 5798.22,5242.5 h60
  text "PTH" at 6947.88,5242.5 h60
  text "Round" at 7453.76,5242.5 h60
  text "Top Layer - Bottom Layer" at 8187.56,5242.5 h60
  text "Pad" at 9687.11,5242.5 h60
  text "Rectangle" at 10276.96,5242.5 h60
  text "6" at 5198.38,5092.5 h60
  text "63.00mil (1.600mm)" at 5798.22,5092.5 h60
  text "PTH" at 6947.88,5092.5 h60
  text "Round" at 7453.76,5092.5 h60
  text "Top Layer - Bottom Layer" at 8187.56,5092.5 h60
  text "Pad" at 9687.11,5092.5 h60
  text "Rounded" at 10276.96,5092.5 h60
  text "18" at 5198.38,4942.5 h60
  text "40.00mil (1.016mm)" at 5798.22,4942.5 h60
  text "PTH" at 6947.88,4942.5 h60
  text "Round" at 7453.76,4942.5 h60
  text "Top Layer - Bottom Layer" at 8187.56,4942.5 h60
  text "Pad" at 9687.11,4942.5 h60
  text "(Mixed)" at 10276.96,4942.5 h60
  text "21" at 5198.38,4792.5 h60
  text "7.87mil (0.200mm)" at 5798.22,4792.5 h60
  text "PTH" at 6947.88,4792.5 h60
  text "Round" at 7453.76,4792.5 h60
  text "Top Layer - Bottom Layer" at 8187.56,4792.5 h60
  text "Via" at 9687.11,4792.5 h60
  text "Rounded" at 10276.96,4792.5 h60
  text "112" at 5198.38,4642.5 h60
  text "16.00mil (0.406mm)" at 5798.22,4642.5 h60
  text "PTH" at 6947.88,4642.5 h60
  text "Round" at 7453.76,4642.5 h60
  text "Top Layer - Bottom Layer" at 8187.56,4642.5 h60
  text "Via" at 9687.11,4642.5 h60
  text "Rounded" at 10276.96,4642.5 h60
  text "820" at 5198.38,4492.5 h60
  text "10.00mil (0.254mm)" at 5798.22,4492.5 h60
  text "PTH" at 6947.88,4492.5 h60
  text "Round" at 7453.76,4492.5 h60
  text "Top Layer - Bottom Layer" at 8187.56,4492.5 h60
  text "Via" at 9687.11,4492.5 h60
  text "Rounded" at 10276.96,4492.5 h60
  text "985 Total" at 5198.38,4342.5 h60
  text ".Layer_Name" at 577,-858.49 h60
M17 Embedded Cavity:
  text ".Layer_Name" at 577,-858.49 h60
M18 Embedded Assembly:
  text ".Layer_Name" at 577,-858.49 h60
M19 Embedded Keepout:
  text ".Layer_Name" at 577,-858.49 h60

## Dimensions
0,0 to 4950,0 on M2 Board Dimensions
0,0 to 0,3450 on M2 Board Dimensions
0,-400 to 1000,-400 on M2 Board Dimensions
